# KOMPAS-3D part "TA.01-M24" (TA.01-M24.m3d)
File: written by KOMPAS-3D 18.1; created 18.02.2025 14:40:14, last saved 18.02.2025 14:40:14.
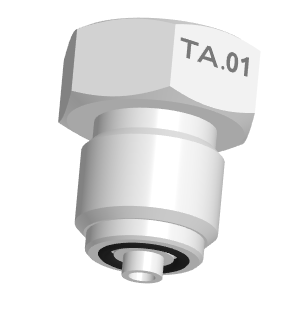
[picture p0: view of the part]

Document properties: Автор: Admin; Полное имя файла: Z:\Элхарт\БД\3D модели\ЭЛХАРТ\TA.01-M24\TA.01-M24.m3d

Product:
- Part/product: TA.01-M24

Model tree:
1. Операция без истории:1  (labels: TA.01-M24)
